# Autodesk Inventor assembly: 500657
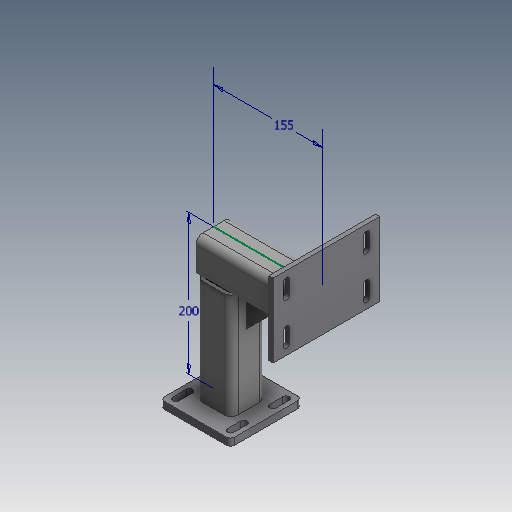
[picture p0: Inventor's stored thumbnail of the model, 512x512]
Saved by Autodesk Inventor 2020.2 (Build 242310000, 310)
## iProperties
_SolveAssemblyDoc: Frame Generator Solve Assembly
_Version: 15.0.0
Shininess: 0.0
Length Units: 11269
Angle Units: 11279
Time Units: 11290
Mass Units: 11283
Length Display Precision: 3
Angle Display Precision: 2
Compacted: True
Created: 2000-02
Part Number: 500657
Document SubType Name: Assembly
Designer: sspink
Mass: 1800.88 g
Surface Area: 1724.05 cm^2
Volume: 452.292 cm^3
Density: 3.98168 g/cm^3
Density: 0.0
Volumn: 0.0
Area: 0.0
PropertySet Name: Model Information
Control State: 0
Checked Out: False
Master: False
Dimensions: 265x152x186 mm
Mass: 1,801 kg
DocNumber: 500657.iam
Folder: 01 - Themengebiete\Simplification\01 - Packaging machine\
VDS_Category: 3D Komponenten
Author: sspink
Revision Number: -
Title: 500657
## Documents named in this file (6)
- D:\07 - DEMODATEN\OTX 2019 - Dataset - UPDATE - Dez2019\Designs\07-Packing machine\500657.iam
- D:\07 - DEMODATEN\OTX 2019 - Dataset - UPDATE - Dez2019\Designs\07-Packing machine\Parts\ADSK-011633.ipt
- D:\07 - DEMODATEN\OTX 2019 - Dataset - UPDATE - Dez2019\Designs\07-Packing machine\Parts\ADSK-011637.ipt
- D:\07 - DEMODATEN\OTX 2019 - Dataset - UPDATE - Dez2019\Designs\07-Packing machine\Parts\ADSK-014438.ipt
- D:\07 - DEMODATEN\OTX 2019 - Dataset - UPDATE - Dez2019\Designs\07-Packing machine\500657\Frame\ADSK-014439.iam
- D:\07 - DEMODATEN\OTX 2019 - Dataset - UPDATE - Dez2019\Designs\07-Packing machine\Parts\ADSK-011642.ipt
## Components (5 placed, 5 different names)
1. ADSK-014438:1
2. ADSK-011633:1 — Passend:8, Passend:9, Passend:10, Passend:15, Fluchtend:16
3. ADSK-011637:1 — Passend:11, Passend:12, Fluchtend:14
4. ADSK-014439:1 [sub-assembly] — Passend:8, Passend:9, Passend:10, Passend:11, Passend:12, Fluchtend:14, Passend:13, Fluchtend:15, Passend:14, Passend:15, Fluchtend:16
5. ADSK-011642:1 — Passend:13, Fluchtend:15, Passend:14
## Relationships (11: Mate 8, Flush 3)
- Passend:8 [Mate]: ADSK-011633:1 ↔ ADSK-014439:1
- Passend:9 [Mate]: ADSK-011633:1 ↔ ADSK-014439:1
- Passend:10 [Mate]: ADSK-011633:1 ↔ ADSK-014439:1
- Passend:11 [Mate]: ADSK-011637:1 ↔ ADSK-014439:1
- Passend:12 [Mate]: ADSK-011637:1 ↔ ADSK-014439:1
- Fluchtend:14 [Flush]: ADSK-011637:1 ↔ ADSK-014439:1
- Passend:13 [Mate]: ADSK-014439:1 ↔ ADSK-011642:1
- Fluchtend:15 [Flush]: ADSK-014439:1 ↔ ADSK-011642:1
- Passend:14 [Mate]: ADSK-014439:1 ↔ ADSK-011642:1
- Passend:15 [Mate]: ADSK-011633:1 ↔ ADSK-014439:1
- Fluchtend:16 [Flush]: ADSK-011633:1 ↔ ADSK-014439:1
